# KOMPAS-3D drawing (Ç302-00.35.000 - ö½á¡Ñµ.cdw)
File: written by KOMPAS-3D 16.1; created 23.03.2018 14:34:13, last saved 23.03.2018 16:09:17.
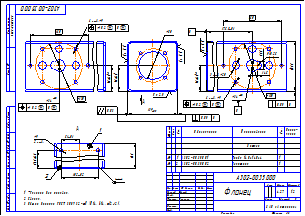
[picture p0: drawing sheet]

Sheet 1: A3, landscape

Title block, sheet 1: name: Фланец; designation: А302-00.35.000; mass: 4,27; scale: 1:2; sheets: 1; organisation: ЗАО «Астерион»; sheet format: A3; stored path: \\192.168.87.28\Konstructor_doc\Мембранные насосы\Мембранный электропривод\А302-00.00.000 - ASTRA-302 (МЭ200)\Чертежи\А302-00.35.000 - Фланец.cdw; drawn by: Милов; technical control: Лучихин

Views: Вид 1, Спереди, Проекционный вид 2, Местный разрез 1, Проекционный вид 3, Вид по стрелке 4
Referenced files in Z:\Мембранные насосы\Мембранный электропривод\А302-00.00.000 - ASTRA-302 (МЭ200)\3Д\: А302-00.35.000 - Фланец.a3d, А302-00.35.001 - Труба 140х140х4.m3d, А302-00.35.002 - Пластина.m3d
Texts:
  Ra 2,5
  *Размеры для справок.
  Сварка.
  Общие допуски ГОСТ 30893.2-mK (H14, h14,  t2/2).
  Пластина
  Труба 140х140х4
Dimensions and other numbers on the sheet: 80; 72±0,1; 139; 0,03; 0,05; 160; 130; 6 отв.; 9; 34; 3 отв.; 20; 175,8±0,1; 139,5; 14,5; 20,5; 10,25; 269; 249±0,3; 2 отв.; 102±0,2; 1; 2; 51±0,1; 1:2; 4,27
